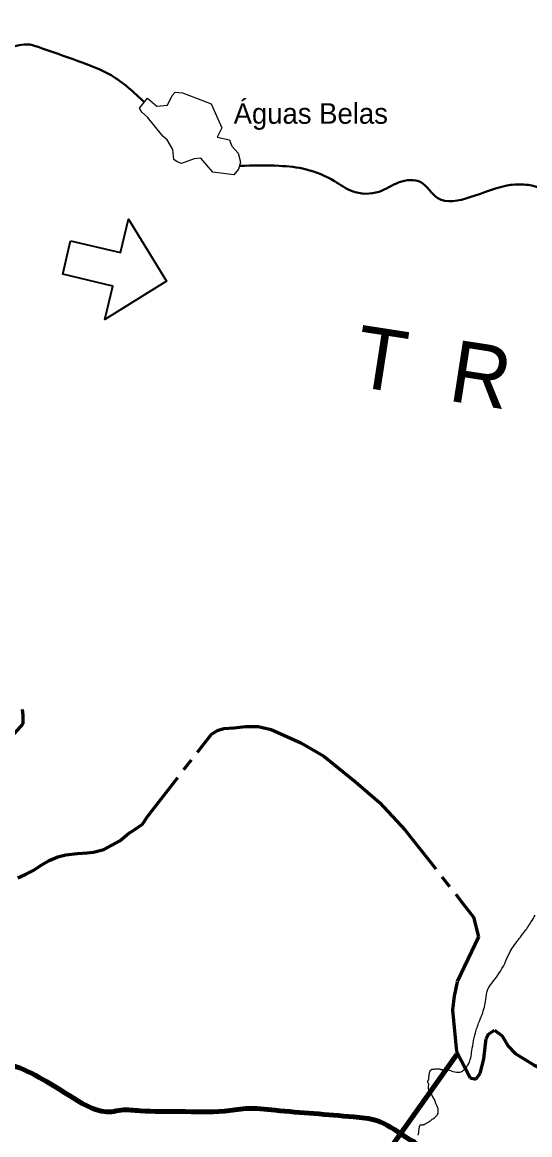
# Model space of a CAD drawing. Extents: x -1643653 to 4543381, y 1624270 to 13878484.
# Drawn here: x 702563 to 714916, y 8967746 to 8994810 of the extents above; entities that cross this region are included whole.
import ezdxf

# ---------------------------------------------------------------- set-up
doc = ezdxf.new("R2010")
doc.units = 0
doc.header["$LTSCALE"] = 200
doc.linetypes.add('LONG_DASH_SHORT_DASH', pattern=[9.9, 6, -1.2, 1.5, -1.2])
for name, color, linetype, lineweight in [('12', 7, 'Continuous', 25), ('21', 7, 'Continuous', 25), ('24', 7, 'Continuous', 25), ('26', 7, 'Continuous', 106), ('28', 7, 'Continuous', 53), ('53', 7, 'Continuous', 106), ('60', 7, 'Continuous', 13), ('7', 7, 'LONG_DASH_SHORT_DASH', 60), ('9', 7, 'Continuous', 90)]:
    doc.layers.add(name, color=color, linetype=linetype, lineweight=lineweight)
doc.layers.add('41', color=7, linetype='Continuous')
doc.layers.add('55', color=7, linetype='Continuous')

msp = doc.modelspace()

# ---------------------------------------------------------------- linework, layer by layer
at = {"layer": '12', "lineweight": 40}
for points in [[(707857.4, 8991316.5), (708816.1, 8991316.5), (709474.3, 8991230.6), (710161.1, 8990944.3), (710590.4, 8990700.9), (711248.6, 8990686.6), (711735.1, 8990915.7), (712264.5, 8990915.7), (712679.5, 8990529.1), (713459.3, 8990550.6), (714446.6, 8990851.2), (714875.8, 8990851.2), (716206.5, 8990378.8), (717666, 8990507.7), (718782.1, 8990722.4), (719468.9, 8990507.7), (719984, 8990550.6), (720456.2, 8990722.4), (720756.7, 8990722.4), (721529.3, 8991624.3), (722387.9, 8992569.1), (722731.3, 8993599.9), (723418.1, 8994201.1), (724233.7, 8994587.6), (725092.2, 8995790.2), (725521.5, 8996348.5), (725821.9, 8996777.9), (726294.1, 8996906.8), (726980.9, 8996992.7), (727324.3, 8997078.6), (727624.8, 8997422.2), (728054.1, 8997551), (728783.8, 8997508.1), (729857, 8997765.7), (730715.5, 8998109.3), (731445.2, 8998495.8), (732561.3, 8999097.1), (733119.3, 8999311.8), (734192.5, 8999655.4), (734750.5, 8999870.1), (735265.6, 8999870.1), (736639.3, 8999483.6)], [(699285.5, 8993014.3), (700711.7, 8993635.6), (701584.6, 8994007.8), (702420.2, 8994236.9), (702677.6, 8994271.5), (702949.6, 8994208.3), (703922.6, 8993864.7), (704723.8, 8993521.1), (705539.4, 8992862.6)]]:
    msp.add_spline(points, degree=3, dxfattribs=at)
at = {"layer": '21'}
msp.add_lwpolyline([(705610.4, 8992963.2), (705837.4, 8992771.1), (706099.4, 8992788.6), (706212.9, 8993024.4), (706282.8, 8993111.8), (706466.2, 8993094.3), (706806.7, 8992963.2), (707164.8, 8992823.5), (707418, 8992238.2), (707304.5, 8992011.1), (707610.1, 8991949.9), (707662.5, 8991792.7), (707819.7, 8991626.7), (707872.1, 8991408.3), (707828.5, 8991233.6), (707714.9, 8991093.9), (707269.6, 8991155), (707199.7, 8991163.8), (706911.5, 8991504.4), (706745.6, 8991487), (706440, 8991373.4), (706335.2, 8991417.1), (706256.6, 8991469.5), (706230.4, 8991714.1), (706090.7, 8991949.9), (705985.9, 8992037.3), (705610.4, 8992500.3), (705470.7, 8992622.6), (705418.2, 8992718.7)], close=True, dxfattribs=at)
at = {"layer": '24'}
for points in [[(712690, 8968326.5), (712690.3, 8968347.4), (712687.7, 8968373.4), (712681.1, 8968396.6), (712670.7, 8968420.3), (712652.7, 8968457.2), (712635.7, 8968489.6), (712630.2, 8968501.8), (712618.7, 8968536.4), (712612.4, 8968563.2), (712607.7, 8968581.2), (712602.5, 8968594.8), (712582.9, 8968625.7), (712571.7, 8968645.8), (712556.8, 8968667.7), (712550.1, 8968679.4), (712536.4, 8968711.4), (712526.2, 8968733.8), (712504.6, 8968767.7), (712488.9, 8968793.2), (712481.3, 8968803.6), (712470.9, 8968814.8), (712457.3, 8968837.7), (712452.4, 8968855.4), (712449, 8968868.7), (712448.2, 8968908.5), (712449.5, 8968918.2), (712455.2, 8968939), (712459.4, 8968952.5), (712458.9, 8968964.7), (712457.1, 8968975.7), (712452.6, 8968990.5), (712442.7, 8969009.5), (712437.8, 8969020.8), (712436.7, 8969027), (712435.9, 8969046.5), (712437.7, 8969054.3), (712441.6, 8969067.1), (712447.9, 8969077), (712452.6, 8969085.3), (712457.3, 8969101), (712459.4, 8969116.1), (712459.2, 8969139.7), (712464.6, 8969179.8), (712468.8, 8969203.8), (712475.9, 8969243.4), (712486.1, 8969286.9), (712490, 8969295), (712495.5, 8969304.8), (712515.6, 8969325.4), (712535.4, 8969337.4), (712546.3, 8969339.7), (712566.2, 8969339.7), (712586.8, 8969343.1), (712612.1, 8969347.5), (712654.3, 8969353), (712686.3, 8969352.2), (712723.6, 8969346.3), (712751, 8969335.6), (712759.6, 8969332.7), (712773.7, 8969331.9), (712781.3, 8969330.9), (712808.4, 8969328.7)], [(712202.5, 8967733.4), (712209.5, 8967765.4), (712210.5, 8967781.3), (712212.4, 8967793.3), (712218.1, 8967841.4), (712223.9, 8967871.9), (712226.8, 8967890.7), (712231.7, 8967931.5), (712234.9, 8967950.2), (712241.1, 8967974.7), (712244.5, 8967981.5), (712250, 8967986.4), (712254.2, 8967989), (712260.7, 8967989.8), (712272.7, 8967986.4), (712281.8, 8967985.6), (712298.5, 8967986.2), (712318.1, 8967989.3), (712330.9, 8967991.9), (712343.6, 8967997.4), (712367.4, 8968008.8), (712388.5, 8968021.1), (712416.3, 8968035.5), (712431.5, 8968043.6), (712450, 8968054.8), (712468.2, 8968066.3), (712491.7, 8968082.7), (712508.9, 8968095.7), (712514.9, 8968101.2), (712528.9, 8968113.6), (712541.7, 8968122.4), (712558.6, 8968135.7), (712577.2, 8968148), (712594.1, 8968160.2), (712604.8, 8968167.2), (712626.6, 8968188), (712644.6, 8968206), (712660.5, 8968224.8), (712673, 8968242.2), (712683.5, 8968264.3), (712688.2, 8968281), (712689.2, 8968296.1), (712690, 8968326.5)]]:
    msp.add_lwpolyline(points, dxfattribs=at)
at = {"layer": '24', "lineweight": 53}
msp.add_spline([(701485.3, 8987819.6), (701680.1, 8988244.2), (701892.7, 8988551.5), (702105.4, 8988953.4), (702223.5, 8989449.8), (702270.7, 8989993.5), (702309.6, 8990518.5), (702309.6, 8990655.6), (702138.3, 8990838.4), (702058.3, 8990964.1), (702001.2, 8991901.1), (702058.3, 8992621), (701978.4, 8993226.6), (701909.9, 8993763.7), (702081.2, 8994266.4), (702161.1, 8994392.1), (702183.9, 8994563.5), (702046.9, 8995123.4), (702104, 8995717.6), (702012.6, 8996106.1), (702024.1, 8996688.9), (702218.2, 8997317.3), (702583.6, 8998197.2), (702800.6, 8998757.1), (703097.5, 8998997), (703668.5, 8999499.8), (703862.6, 8999602.7), (704182.3, 9000288.2), (704330.8, 9000551.1), (704730.5, 9000813.9), (705038.8, 9000962.4), (705347.1, 9001213.8), (705381.3, 9001270.9), (705655.4, 9001636.6), (705815.3, 9002230.8), (706009.4, 9002665), (706066.5, 9002984.9), (706671.7, 9003224.9), (706877.3, 9003270.6), (707231.3, 9003761.9), (707585.3, 9004161.9), (707722.3, 9004687.5), (707825.1, 9005041.7), (708019.2, 9005304.5), (708236.2, 9005453.1), (708384.6, 9005795.9), (708384.6, 9006332.9), (708430.3, 9006618.6), (708841.4, 9007144.2), (708978.5, 9007384.2), (709047, 9007818.4), (709081.2, 9008046.9), (708944.2, 9008412.6), (708955.6, 9008766.8), (708921.3, 9009223.9), (709252.5, 9009509.5), (709549.4, 9009646.7), (709720.7, 9009715.2), (709869.2, 9009875.2), (709949.1, 9010035.2), (709949.1, 9010389.4), (710097.6, 9010549.4), (710234.6, 9011017.8), (710325.9, 9011189.2), (710588.6, 9011383.5), (710679.9, 9011589.2), (710679.9, 9011772), (710531.5, 9012137.7), (710394.5, 9012434.8), (710405.9, 9012606.2), (710508.6, 9012777.6), (710885.5, 9013451.7), (711056.8, 9013646), (711102.5, 9013874.5), (711068.2, 9014365.8), (711022.5, 9014708.7), (710805.5, 9015188.6), (710759.9, 9015325.7), (710828.4, 9015462.8), (710908.3, 9015599.9), (710817, 9015782.8), (710668.5, 9015942.7), (710394.5, 9016228.4), (710405.9, 9016376.9), (710611.4, 9016708.3), (710634.2, 9017119.7), (710645.7, 9017393.9), (710759.9, 9017599.6), (710896.9, 9017919.5), (710942.6, 9018182.3), (710771.3, 9018513.7)], degree=3, dxfattribs=at)
at = {"layer": '24'}
msp.add_spline([(712808.4, 8969328.7), (712919.9, 8969322.8), (713050.3, 8969283.7), (713210.1, 8969269.8), (713421.9, 8969461.2), (713507.8, 8969785.2), (713611.3, 8970290), (713710.5, 8970556), (713756, 8970671), (713844.9, 8971036.8), (713896, 8971286.1), (714036.6, 8971490.7), (714335.6, 8971975.9), (714439.2, 8972202.6), (714548.2, 8972369.4), (714774.9, 8972667.5), (714944, 8972914.8), (715048.1, 8973090.5)], degree=3, dxfattribs=at)
at = {"layer": '26'}
for points in [[(676174.9, 8960921), (676589.7, 8959851), (677298.5, 8959085), (677905.7, 8958370.4), (678108.1, 8958127.9), (678628.8, 8957871.5), (679175.3, 8957678.5), (679634.1, 8957740.2), (680271.7, 8957890.1), (680680.6, 8958130.1), (682556.7, 8958821.8), (683435.7, 8958881.7), (684580.7, 8958673.6), (685598.3, 8958453.2), (686374.5, 8958348.3), (687212.1, 8957836.1), (687682.2, 8957630.7), (688306.1, 8957615.5), (689591.9, 8957533.9), (690585.7, 8957606.1), (691389.1, 8957793.5), (691759.3, 8957957.3), (692919.9, 8958245), (693572, 8958700.2), (694136.4, 8959422.7), (694705.3, 8960908.2), (694927.7, 8961937.4), (695327.4, 8962800.5), (695494.2, 8963028.7), (696954.2, 8966672.4), (698159, 8968028.2), (699003.1, 8968647.8), (699373.7, 8968875.2), (699705.8, 8969051.9), (700930.8, 8969479.2), (701631.8, 8969565.3), (702395, 8969409.6), (703157, 8969037.7), (703804.2, 8968640.8), (704732, 8968306.3), (704974.2, 8968343.5), (705432.6, 8968328.9), (706400.3, 8968312.2), (707482.9, 8968320.5), (708005.4, 8968381.9), (708718.3, 8968340.8), (709660.3, 8968260.6), (710627.7, 8968180.3), (711187.5, 8968089), (711873, 8967704.7), (712851.5, 8967319.2), (713361.3, 8967393.4), (714238.5, 8967122.7), (715674, 8966506.4), (716373.4, 8966312.8), (717313.4, 8965902), (718673.1, 8965375), (719658.3, 8965140.1)], [(691088.7, 8957705.7), (691389.1, 8957793.5), (691759.3, 8957957.3), (692919.9, 8958245), (693572, 8958700.2), (694136.4, 8959422.7), (694705.3, 8960908.2), (694927.7, 8961937.4), (695327.4, 8962800.5), (695494.2, 8963028.7), (696954.2, 8966672.4), (698159, 8968028.2), (699003.1, 8968647.8), (699373.7, 8968875.2), (699705.8, 8969051.9), (700930.8, 8969479.2), (701631.8, 8969565.3), (702395, 8969409.6), (703157, 8969037.7), (703804.2, 8968640.8), (704732, 8968306.3), (704974.2, 8968343.5), (705432.6, 8968328.9), (706400.3, 8968312.2), (707482.9, 8968320.5), (708005.4, 8968381.9), (708718.3, 8968340.8), (709660.3, 8968260.6), (710627.7, 8968180.3), (711187.5, 8968089), (711873, 8967704.7), (712851.5, 8967319.2), (713361.3, 8967393.4), (714238.5, 8967122.7), (715674, 8966506.4), (716373.4, 8966312.8), (717313.4, 8965902), (718673.1, 8965375), (719658.3, 8965140.1)]]:
    msp.add_spline(points, degree=3, dxfattribs=at)
at = {"layer": '28'}
for points in [[(707482.9, 8968320.5), (706400.3, 8968312.2), (705432.6, 8968328.9), (704974.2, 8968343.5), (704732, 8968306.3), (703804.2, 8968640.8), (703157, 8969037.7), (702395, 8969409.6), (701631.8, 8969565.3), (700930.8, 8969479.2), (699705.8, 8969051.9), (699373.7, 8968875.2), (699003.1, 8968647.8), (698159, 8968028.2), (696954.2, 8966672.4), (695494.2, 8963028.7), (695327.4, 8962800.5), (694975.6, 8962075.5)], [(709660.3, 8968260.6), (708718.3, 8968340.8), (708005.4, 8968381.9), (707482.9, 8968320.5)], [(712133.2, 8967582.6), (711873, 8967704.7), (711187.5, 8968089), (710627.7, 8968180.3), (709660.3, 8968260.6)]]:
    msp.add_spline(points, degree=3, dxfattribs=at)
at = {"layer": '53', "lineweight": 35}
msp.add_lwpolyline([(703738.7, 8989488.7), (704955.9, 8989204.2), (705145.6, 8990015.6), (706078.2, 8988513.8), (704576.5, 8987581.2), (704766.2, 8988392.6), (703549, 8988677.1)], close=True, dxfattribs=at)
at = {"layer": '60', "lineweight": 25}
msp.add_spline([(814781, 9009175.5), (814787.2, 9009173.4), (814796.9, 9009173.4), (814799.4, 9009172.4), (814805.1, 9009174.5), (814805.6, 9009176.5), (814811.7, 9009179.5), (814811.7, 9009179.5), (814801.5, 9009181), (814790.7, 9009181.5), (814784.1, 9009183.1), (814777.4, 9009185.1), (814778.4, 9009175.5)], degree=3, dxfattribs=at)
at = {"layer": '7'}
for points in [[(702561.1, 8978097.3), (702577.6, 8977955.8), (702575.7, 8977743.8), (701504.8, 8976551.4)], [(702455.1, 8973998.6), (702650.3, 8974085.3), (702827.8, 8974172.1), (703041.1, 8974311.7), (703218.8, 8974416.2), (703431.7, 8974502.7), (703626.6, 8974554), (703909.7, 8974586.9), (704139.6, 8974602.6), (704298.9, 8974618.9), (704546.9, 8974687.4), (704742.3, 8974791.8), (704937.7, 8974896.1), (705151.3, 8975071), (705275.8, 8975158.3), (705489.1, 8975297.8), (705614.5, 8975491.1), (707169.7, 8977492.2), (707311.9, 8977579.3), (707471.4, 8977630.9), (707719, 8977646.5), (708002.2, 8977679.4), (708302.6, 8977676.8), (708620.2, 8977603.3), (709342.2, 8977279.1), (709905.1, 8976956.1), (710677.5, 8976331), (711256.6, 8975831.2), (711887.1, 8975154.3), (713233.6, 8973446.3), (713548.2, 8973037.2), (713667.8, 8972559), (713145.8, 8971468), (713072, 8971115.2), (713033.8, 8970779.8), (713131.2, 8969771.7), (713339.8, 8969363.5), (713461.5, 8969132.7), (713602.6, 8969096.1), (713709.9, 8969236.6), (713801.3, 8969589.2), (713858.6, 8970083.5), (713912.6, 8970189.1), (714054.9, 8970293.8), (714248.1, 8970150.8), (714387.4, 8969902.2)], [(714387.4, 8969902.2), (714562.6, 8969724), (714791.2, 8969580.7), (715019.8, 8969437.3), (715266.3, 8969329.2), (715566.5, 8969291.3), (716240, 8969497.5), (716452.6, 8969548.7), (716647.3, 8969582.3), (716912.5, 8969580.1), (717194.9, 8969524.6), (717616.1, 8969176.7), (717779.5, 8968954.6), (717981.6, 8968510.6), (718255.9, 8967518.7), (718550, 8966774), (718899, 8966240.8), (719126.6, 8965991.5), (719265.4, 8965689.9), (719369.1, 8965406.3), (719491, 8965193.2), (719658.3, 8965140.1)]]:
    msp.add_lwpolyline(points, dxfattribs=at)
at = {"layer": '9'}
msp.add_lwpolyline([(691582, 8951218.7), (697371.2, 8956056), (705081.2, 8958366.8), (713138.6, 8969695)], dxfattribs=at)

# ---------------------------------------------------------------- texts
at = {"layer": '41'}
msp.add_text('Águas Belas', height=500, dxfattribs=at).set_placement((707709, 8992340.3))
at = {"layer": '55'}
msp.add_text('T  R  A  N  S  I  Ç  Ã  O', height=1500, rotation=351.193, dxfattribs=at).set_placement((710586.3, 8985966.8))

doc.saveas('drawing.dxf')
